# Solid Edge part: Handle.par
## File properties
Author: jmrobins
Template: Normal.par
Last saved by: rkriggs
Revision: 53
Application: Solid Edge
Density: 0.000008027 kg/mm^3
Accuracy: 0.99
Material: Stainless Steel, 303
Face Style: Steel
Fill Style: ANSI32(Steel)
Virtual Style: Stainless steel
Coef. of Thermal Exp: 1.7e-05
Thermal Conductivity: 17.0
Specific Heat: 502.0
Modulus of Elasticity: 193053196000.0
Poission's Ratio: 0.29
Yield Stress: 255106009.0
Ultimate Stress: 579159588.0
Elongation: 0.0
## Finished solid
Body 1: solid body, 28 faces, 58 edges, 32 vertices.
  Faces by surface: plane 11, cylinder 8, blend 6, torus 3
  Edges by curve: circle 26, line 20, intersection 12
Bounding box of the edges (mm; curved faces can reach further): 108.000 x 46.000 x 18.000, from (-23, -23, -9) to (85, 23, 9).
Cylindrical faces by radius (mm): R5 x5, R7.5 x2, R18 x1
Toroidal faces (ring radius, tube radius in mm): R1.834 r23 x1, R25.1578 r2 x2
Planar faces by outward normal: +x 2, +y 2, +z 3, -y 2, -z 2
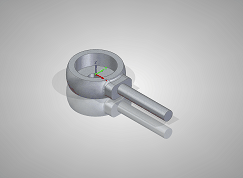
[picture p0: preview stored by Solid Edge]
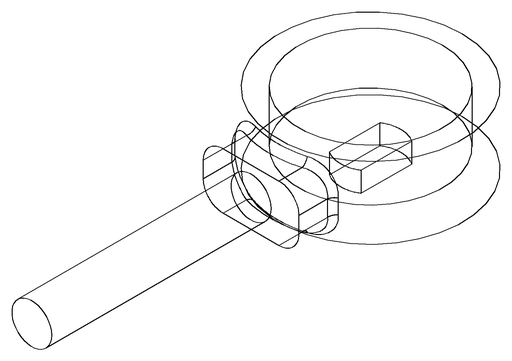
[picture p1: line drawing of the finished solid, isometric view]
